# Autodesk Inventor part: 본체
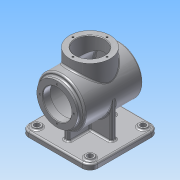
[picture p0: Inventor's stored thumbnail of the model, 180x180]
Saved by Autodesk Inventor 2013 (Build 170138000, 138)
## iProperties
Created: 2015-07
Part Number: 본체
Material: 알루미늄 6061
Document SubType Name: Modeling
Designer: Administrator
Density: 2.71 g/cm^3
Mass: 1277.74 g
Surface Area: 1267.61 cm^2
Volume: 471.49 cm^3
Author: Administrator
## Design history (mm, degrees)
sketch "스케치1"
  geometry: C1 r 45 at (0, 0); 1 further point
  constraints: 1 centre point, 1 coincident
  dimensions: "d0" = 90 diameter of C1
extrude "돌출1" new body sketch "스케치1" stored distance "d1" = 110; taper "d2" = 0 deg
sketch "스케치4"
  geometry: L1 (40, 48)-(40, -48); L2 (40, -48)-(0, -48); L3 (0, 48)-(40, 48); L4 (45, -55)-(-45, -55) reference; L5 (-45, -55)-(-45, 55) reference; L6 (-45, 55)-(45, 55) reference; L7 (45, 55)-(45, -55) reference; L8 (0, 48)-(0, -48); 1 further point
  constraints: 8 end point, 4 parallel, 1 perpendicular, 1 vertical
  dimensions: "d10" = 5 distance between parallel lines of L7 L1; "d11" = 7 distance between parallel lines of L3 L6; "d12" = 7 distance between parallel lines of L4 L2; "d14" = 40 distance between parallel lines of L1 L8
revolve "회전1" sketch "스케치4" stored, may be unused: angle "d15" = 90 deg
sketch "스케치5"
  geometry: C1 r 45 at (0, 0) reference; C2 r 38 at (0, 0)
  constraints: 1 centre point, 1 coincident
  dimensions: "d16" = 76 diameter of C2
extrude "돌출3" join sketch "스케치5" distance "d17" = 7; taper "d18" = 0 deg
sketch "스케치6"
  geometry: C1 r 38 at (0, 0) reference; C2 r 27 at (0, 0)
  constraints: 1 centre point, 1 coincident
  dimensions: "d19" = 54 diameter of C2
extrude "돌출4" cut sketch "스케치6" distance "d20" = 14; taper "d21" = 0 deg
node "작업 평면1"
sketch "스케치7"
  geometry: L1 (-65, 65)-(65, 65); L2 (65, 65)-(65, -65); L3 (65, -65)-(-65, -65); L4 (-65, -65)-(-65, 65); L5 (-65, 65)-(65, -65); L6 (65, 65)-(-65, -65); 1 further point
  constraints: 12 end point, 2 midpoint, 2 parallel, 1 horizontal, 1 perpendicular
  dimensions: "d23" = 130 distance of L2.end L3.end; "d24" = 130 distance of L1.end L2.end
extrude "돌출5" join sketch "스케치7" distance "d25" = 10; taper "d26" = 0 deg
sketch "스케치8"
  geometry: L1 (-65, 65)-(-65, -65) reference; L2 (-5, 45)-(-5, 5); L3 (-5, 5)-(-5, 45); L4 (-5, 45)-(5, 45); L5 (5, 45)-(5, 5); L6 (5, 5)-(45, 5); L7 (45, 5)-(45, -5); L8 (45, -5)-(5, -5); L9 (5, -5)-(5, -45); L10 (5, -45)-(-5, -45); L11 (-5, -45)-(-5, -5); L12 (-5, -5)-(-45, -5); L13 (-45, -5)-(-45, 5); L14 (-45, 5)-(-5, 5); 3 further points
  constraints: 26 end point, 9 parallel, 7 collinear, 2 midpoint, 2 perpendicular, 1 horizontal alignment, 1 vertical alignment
  dimensions: "d27" = 10 distance of L2.start L4.end; "d29" = 10 distance of L12.end L13.end; "d30" = 90 distance between parallel lines of L10 L4; "d31" = 90 distance between parallel lines of L7 L13; "d32" = 10 distance between parallel lines of L9 L11
extrude "돌출6" join sketch "스케치8" stored distance "d33" = 10; taper "d34" = 0 deg
node "작업 평면3"
sketch "스케치9"
  geometry: C1 r 38 at (0, 0); 1 further point
  constraints: 1 centre point, 1 coincident
  dimensions: "d37" = 76 diameter of C1
extrude "돌출7" join sketch "스케치9" stored distance "d38" = 10; taper "d39" = 0 deg
sketch "스케치10"
  geometry: C1 r 38 at (0, 0) reference; C2 r 27 at (0, 0)
  constraints: 1 centre point, 1 coincident
  dimensions: "d40" = 54 diameter of C2
extrude "돌출8" cut sketch "스케치10" distance "d41" = 50; taper "d42" = 0 deg
fillet "모깎기1" dims "d43" = 3
fillet "모깎기2" dims "d44" = 3
fillet "모깎기3" dims "d45" = 15
sketch "스케치11"
  geometry: C1 r 7.5 at (-50, 50); C2 r 7.5 at (-50, -50); A1 r 15 centre (-50, 50) between (-50, 65) and (-65, 50) reference; A2 r 15 centre (-50, -50) between (-65, -50) and (-50, -65) reference; 1 further point
  constraints: 2 centre point, 2 coincident
  dimensions: "d46" = 15 diameter of C1; "d47" = 15 diameter of C2
extrude "돌출9" join sketch "스케치11" distance "d48" = 3; taper "d49" = 0 deg
sketch "스케치12"
  geometry: C1 r 7.5 at (0, 0) reference; C2 r 7.5 at (0, -100) reference; C3 r 5 at (0, 0); C4 r 5 at (0, -100); 1 further point
  constraints: 2 centre point, 2 coincident
  dimensions: "d50" = 10 diameter of C3; "d51" = 10 diameter of C4
extrude "돌출10" cut sketch "스케치12" distance "d52" = 13; taper "d53" = 0 deg
fillet "모깎기5" dims "d55" = 3
sketch "스케치13"
  geometry: C1 r 27 at (0, 0) reference; 1 further point
  constraints: 1 horizontal alignment
  dimensions: "d56" = 32 distance of point (-32, 0) C1.centre
hole "구멍1" sketch "스케치13" at (-32, 0) diameter "d57" = 3.242; stored, may be unused: countersink angle "d61" = 90 deg, drill point angle "d63" = 118 deg; dims "d58" = 8, "d59" = 4, "d60" = 2, "d62" = 10
sketch "스케치14"
  geometry: C1 r 27 at (0, 0) reference; 1 further point
  constraints: 1 vertical alignment
  dimensions: "d67" = 32 distance of C1.centre point (0, 32)
hole "구멍2" sketch "스케치14" at (0, 32) diameter "d68" = 3.242; stored, may be unused: countersink angle "d72" = 90 deg, drill point angle "d74" = 118 deg; dims "d69" = 8, "d70" = 4, "d71" = 2, "d73" = 10
sketch "스케치15"
  geometry: C1 r 42 at (0, 0) reference; 1 further point
  constraints: 1 coincident, 1 other
feature "엠보싱1" sketch "스케치15" dims "d78" = 0.5, "d79" = 0
chamfer "모따기1" distance "d80" = 1; stored, may be unused: second distance "d81" = 2, angle "d82" = 45 deg
node "솔리드1"
mirror "대칭1"
pattern_circular "원형 패턴1" dims angle "d65" = 360 deg
pattern_circular "원형 패턴2" dims angle "d76" = 360 deg
node "투영된 루프2"
node "절단 모서리 투영1"
other parameters: "d22" = -78, "d36" = 62
